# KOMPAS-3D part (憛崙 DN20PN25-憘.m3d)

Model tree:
1. Объединить компоненты:1  (labels: СЕНС DN20PN25)
2. Эскиз:1
3. Операция выдавливания:1
     Расстояние 1 = 14
4. Фаска:1
     Угол = 45; Длина 1 = 2; Длина 2 = 2

Referenced files in D:\Савин\!СЕНСОР\3D для заказчика\!Новый перечень\СЕНС\1. СЕНС\DN20\: СЕНС DN20PN25.a3d
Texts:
  СЕНС DN20PN25-СВ
  ООО НПП Сенсор
  СЕНС DN20PN25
